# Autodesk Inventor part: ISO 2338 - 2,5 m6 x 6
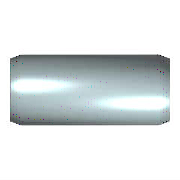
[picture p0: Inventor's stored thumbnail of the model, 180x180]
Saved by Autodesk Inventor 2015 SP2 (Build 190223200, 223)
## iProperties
IsCustomPart: 0
Created: 2012-02
Part Number: ISO 2338 - 2,5 m6 x 6
Material: Stainless Steel, Austenitic
Description: Parallel Pin
Document SubType Name: Modeling
Standard: ISO 2338
Designer: rYan
Standards Organization: DIN
Language: en-US
Size Designation: 2,5 m6 x 6
Categories: <MemberInstance><Categories><Category DisplayName="Fasteners" InternalName="e4da775c-781d-43d5-af7c-5136215cf5a6" Mnemonic="FSTN"><Category DisplayName="Pins" I
Density: 8.03 g/cm^3
Mass: 0.233876 g
Surface Area: 0.552727 cm^2
Volume: 0.0291253 cm^3
Appearance: Halbpoliert
Author: rYan
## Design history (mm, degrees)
sketch "Sketch"
  geometry: C1 r 1.25 at (0, 0); 1 further point
  constraints: 1 centre point, 1 coincident
  dimensions: "d1" = 2.5 diameter of C1 (= NND)
extrude "Body" new body sketch "Sketch" distance "d2" = 6 (= NLG); taper "d3" = 0 deg
chamfer "Chamfer1" distance "d4" = 0.4 (= PHH); stored, may be unused: angle "d5" = 15 deg (= FAWI), second distance "d11" = 0.4 (= PHH)
chamfer "Chamfer2" distance "d8" = 0.4 (= PHH); stored, may be unused: angle "d9" = 15 deg (= FAWI), second distance "d12" = 0.4 (= PHH)
body "Solid1"
other parameters: "NND" = 2.5 [user parameter; used in 1 equation term], "NLG" = 6 [user parameter; used in 1 equation term], "PHH" = 0.4 [user parameter; used in 4 equation terms], "FAWI" = 15 deg [user parameter; used in 2 equation terms], "d13" = 0, "d15" = 0, "d16" = 0, "KAH" = 0 [user parameter]
